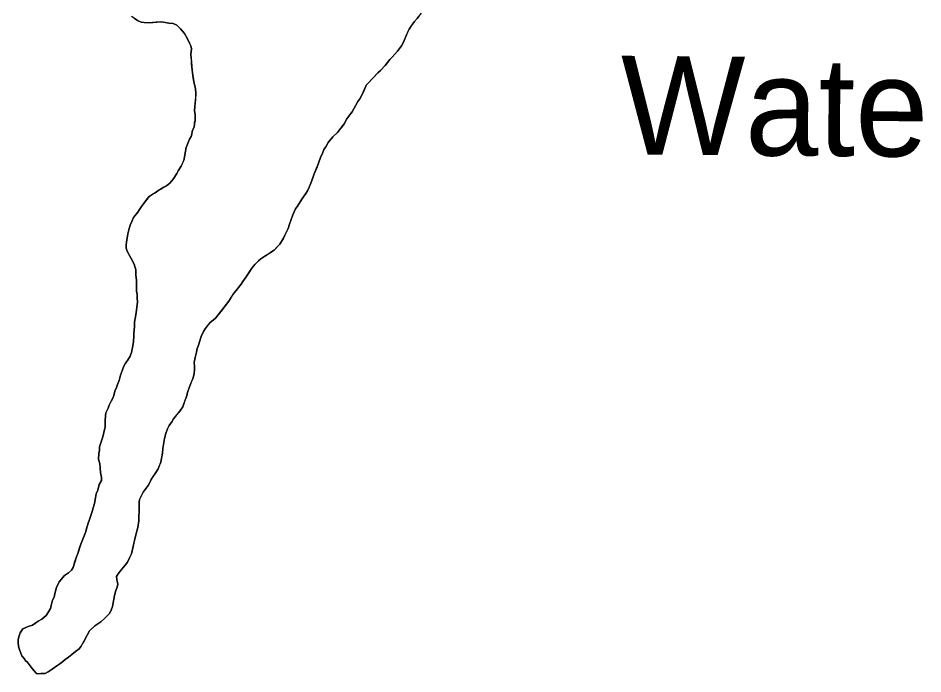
# Model space of a CAD drawing. Extents: x 3172297 to 3210190, y 958463 to 983887.
# Drawn here: x 3189904 to 3190821, y 968442 to 969107 of the extents above; entities that cross this region are included whole.
import ezdxf

# ---------------------------------------------------------------- set-up
doc = ezdxf.new("R2010")
doc.units = 0
for name, color, linetype in [('V-RIVR-IDEN', 7, 'Continuous'), ('V-SITE-VEGE', 7, 'Continuous'), ('V-TOPO-SHOR', 7, 'Continuous')]:
    doc.layers.add(name, color=color, linetype=linetype)

msp = doc.modelspace()

# ---------------------------------------------------------------- linework, layer by layer
at = {"layer": 'V-SITE-VEGE'}
for p, q in [((3190021.54, 969106.91), (3190025.11, 969104.47)), ((3190305.59, 969103.14), (3190308.63, 969106.41)), ((3190308.63, 969106.41), (3190312.89, 969111.76)), ((3190025.11, 969104.47), (3190028.69, 969102.63)), ((3190028.69, 969102.63), (3190031.69, 969102.29)), ((3190031.69, 969102.29), (3190036.8, 969102.24)), ((3190036.8, 969102.24), (3190048.52, 969103.01)), ((3190048.52, 969103.01), (3190051.52, 969102.67)), ((3190051.52, 969102.67), (3190056.62, 969101.72)), ((3190056.62, 969101.72), (3190061.11, 969101.37)), ((3190061.11, 969101.37), (3190065, 969099.82)), ((3190065, 969099.82), (3190068.56, 969096.18)), ((3190068.56, 969096.18), (3190072.71, 969091.33)), ((3190300.4, 969095.69), (3190305.59, 969103.14)), ((3190072.71, 969091.33), (3190075.66, 969085.89)), ((3190294.85, 969082.54), (3190297.02, 969088.22)), ((3190297.02, 969088.22), (3190300.4, 969095.69)), ((3190075.66, 969085.89), (3190077.71, 969081.36)), ((3190077.71, 969081.36), (3190079.18, 969078.64)), ((3190079.18, 969078.64), (3190079.75, 969075.63)), ((3190288.74, 969073.3), (3190292.71, 969078.96)), ((3190292.71, 969078.96), (3190294.85, 969082.54)), ((3190079.75, 969075.63), (3190079.08, 969069.93)), ((3190079.08, 969069.93), (3190080.41, 969054)), ((3190283.27, 969067.35), (3190288.74, 969073.3)), ((3190275.97, 969059.02), (3190280.84, 969064.97)), ((3190280.84, 969064.97), (3190283.27, 969067.35)), ((3190080.41, 969054), (3190080.95, 969049.19)), ((3190258.34, 969040.3), (3190268.67, 969051.3)), ((3190268.67, 969051.3), (3190271.41, 969053.97)), ((3190271.41, 969053.97), (3190275.97, 969059.02)), ((3190080.95, 969049.19), (3190082.36, 969041.06)), ((3190082.36, 969041.06), (3190083.8, 969035.34)), ((3190083.8, 969035.34), (3190084.05, 969030.84)), ((3190252.5, 969028.65), (3190256.51, 969037.92)), ((3190256.51, 969037.92), (3190256.82, 969038.82)), ((3190256.82, 969038.82), (3190258.34, 969040.3)), ((3190083.97, 969023.93), (3190083.3, 969017.33)), ((3190084.05, 969030.84), (3190083.97, 969023.93)), ((3190248.53, 969022.39), (3190250.36, 969025.07)), ((3190250.36, 969025.07), (3190252.5, 969028.65)), ((3190083.3, 969017.33), (3190082.95, 969012.83)), ((3190242.71, 969011.95), (3190244.55, 969015.53)), ((3190244.55, 969015.53), (3190246.38, 969018.51)), ((3190246.38, 969018.51), (3190248.53, 969022.39)), ((3190082.95, 969012.83), (3190083.51, 969009.22)), ((3190083.51, 969009.22), (3190083.43, 969002.31)), ((3190234.46, 968999.72), (3190237.22, 969004.8)), ((3190237.22, 969004.8), (3190242.71, 969011.95)), ((3190082.46, 968996.32), (3190080.93, 968993.33)), ((3190082.8, 968999.32), (3190082.46, 968996.32)), ((3190082.82, 969001.42), (3190082.8, 968999.32)), ((3190083.43, 969002.31), (3190082.82, 969001.42)), ((3190227.76, 968991.09), (3190234.46, 968999.72)), ((3190079.36, 968987.04), (3190077.83, 968984.36)), ((3190079.67, 968987.94), (3190079.36, 968987.04)), ((3190080.93, 968993.33), (3190079.67, 968987.94)), ((3190218.33, 968980.68), (3190222.9, 968986.64)), ((3190222.9, 968986.64), (3190227.76, 968991.09)), ((3190075.67, 968979.28), (3190074.42, 968975.69)), ((3190077.83, 968984.36), (3190075.67, 968979.28)), ((3190215.88, 968976.5), (3190218.33, 968980.68)), ((3190073.15, 968968.49), (3190072.49, 968963.99)), ((3190074.42, 968975.69), (3190073.15, 968968.49)), ((3190210.97, 968966.65), (3190212.5, 968969.64)), ((3190212.5, 968969.64), (3190214.05, 968973.82)), ((3190214.05, 968973.82), (3190215.88, 968976.5)), ((3190072.49, 968963.99), (3190069.41, 968956.82)), ((3190204.16, 968949.01), (3190208.18, 968958.88)), ((3190208.18, 968958.88), (3190210.97, 968966.65)), ((3190064.82, 968949.36), (3190061.15, 968943.7)), ((3190065.44, 968950.86), (3190064.82, 968949.36)), ((3190066.35, 968952.05), (3190065.44, 968950.86)), ((3190069.41, 968956.82), (3190066.35, 968952.05)), ((3190061.15, 968943.7), (3190057.81, 968939.53)), ((3190200.75, 968939.44), (3190204.16, 968949.01)), ((3190045.71, 968931.86), (3190042.98, 968929.79)), ((3190051.75, 968935.4), (3190045.71, 968931.86)), ((3190054.47, 968936.87), (3190051.75, 968935.4)), ((3190057.81, 968939.53), (3190054.47, 968936.87)), ((3190195.83, 968929.28), (3190197.37, 968931.97)), ((3190197.37, 968931.97), (3190199.21, 968935.55)), ((3190199.21, 968935.55), (3190200.75, 968939.44)), ((3190036.93, 968926.25), (3190031.15, 968918.81)), ((3190042.98, 968929.79), (3190036.93, 968926.25)), ((3190187.28, 968916.46), (3190191.56, 968923.32)), ((3190191.56, 968923.32), (3190195.83, 968929.28)), ((3190027.18, 968912.85), (3190025.34, 968910.16)), ((3190029.01, 968915.83), (3190027.18, 968912.85)), ((3190031.15, 968918.81), (3190029.01, 968915.83)), ((3190182.38, 968907.51), (3190185.15, 968913.48)), ((3190185.15, 968913.48), (3190187.28, 968916.46)), ((3190021.08, 968904.81), (3190019.23, 968900.92)), ((3190025.34, 968910.16), (3190021.08, 968904.81)), ((3190179.27, 968897.93), (3190182.38, 968907.51)), ((3190017.69, 968897.04), (3190016.13, 968892.25)), ((3190019.23, 968900.92), (3190017.69, 968897.04)), ((3190177.72, 968893.75), (3190179.27, 968897.93)), ((3190015.19, 968888.35), (3190013.89, 968879.96)), ((3190016.13, 968892.25), (3190015.19, 968888.35)), ((3190173.1, 968883.89), (3190177.72, 968893.75)), ((3190013.56, 968876.96), (3190013.52, 968873.66)), ((3190013.89, 968879.96), (3190013.56, 968876.96)), ((3190163.66, 968871.68), (3190169.43, 968877.92)), ((3190169.43, 968877.92), (3190173.1, 968883.89)), ((3190013.52, 968873.66), (3190014.69, 968870.64)), ((3190014.69, 968870.64), (3190017.04, 968866.41)), ((3190154.28, 968865.48), (3190163.66, 968871.68)), ((3190017.04, 968866.41), (3190018.51, 968863.09)), ((3190018.51, 968863.09), (3190021.75, 968857.35)), ((3190143.97, 968857.18), (3190147.62, 968860.75)), ((3190147.62, 968860.75), (3190150.04, 968862.82)), ((3190150.04, 968862.82), (3190154.28, 968865.48)), ((3190021.75, 968857.35), (3190023.19, 968851.63)), ((3190023.19, 968851.63), (3190023.44, 968846.82)), ((3190135.13, 968844.67), (3190140.93, 968853.32)), ((3190140.93, 968853.32), (3190143.97, 968857.18)), ((3190023.44, 968846.82), (3190023.97, 968841.11)), ((3190023.97, 968841.11), (3190023.88, 968833)), ((3190130.24, 968837.22), (3190131.77, 968839.9)), ((3190131.77, 968839.9), (3190135.13, 968844.67)), ((3190023.88, 968833), (3190024.15, 968829.99)), ((3190024.15, 968829.99), (3190024.71, 968826.98)), ((3190122.93, 968828.59), (3190125.06, 968830.97)), ((3190125.06, 968830.97), (3190130.24, 968837.22)), ((3190024.71, 968826.98), (3190024.67, 968823.38)), ((3190024.67, 968823.38), (3190024.92, 968818.88)), ((3190117.73, 968819.94), (3190122.93, 968828.59)), ((3190024.92, 968818.88), (3190023.93, 968810.78)), ((3190104.33, 968803.27), (3190117.73, 968819.94)), ((3190023.28, 968806.28), (3190022, 968798.79)), ((3190023.93, 968810.78), (3190023.28, 968806.28)), ((3190101.6, 968800.6), (3190104.33, 968803.27)), ((3190021.94, 968793.98), (3190021.27, 968787.68)), ((3190022, 968798.79), (3190021.94, 968793.98)), ((3190093.69, 968791.98), (3190098.57, 968798.23)), ((3190098.57, 968798.23), (3190101.6, 968800.6)), ((3190021.23, 968784.38), (3190020.87, 968778.98)), ((3190021.27, 968787.68), (3190021.23, 968784.38)), ((3190086.9, 968775.54), (3190089.4, 968784.22)), ((3190089.4, 968784.22), (3190091.86, 968789.29)), ((3190091.86, 968789.29), (3190093.69, 968791.98)), ((3190020.87, 968778.98), (3190020.23, 968774.78)), ((3190085.36, 968771.95), (3190086.9, 968775.54)), ((3190018.95, 968767.89), (3190017.71, 968764.3)), ((3190020.23, 968774.78), (3190018.95, 968767.89)), ((3190083.46, 968762.96), (3190084.72, 968768.35)), ((3190084.72, 968768.35), (3190085.36, 968771.95)), ((3190012.82, 968757.15), (3190010.98, 968753.56)), ((3190014.95, 968759.82), (3190012.82, 968757.15)), ((3190017.71, 968764.3), (3190014.95, 968759.82)), ((3190082.5, 968757.87), (3190083.46, 968762.96)), ((3190082.76, 968753.66), (3190082.5, 968757.87)), ((3190009.74, 968750.57), (3190007.88, 968744.89)), ((3190010.98, 968753.56), (3190009.74, 968750.57)), ((3190082.38, 968746.76), (3190082.72, 968750.66)), ((3190082.72, 968750.66), (3190082.76, 968753.66)), ((3190006.32, 968739.5), (3190004.77, 968735.61)), ((3190007.88, 968744.89), (3190006.32, 968739.5)), ((3190078.34, 968734.79), (3190081.43, 968742.26)), ((3190081.43, 968742.26), (3190082.38, 968746.76)), ((3190003.84, 968732.62), (3190002, 968728.73)), ((3190004.77, 968735.61), (3190003.84, 968732.62)), ((3190075.55, 968727.31), (3190078.34, 968734.79)), ((3190000.11, 968721.55), (3189998.27, 968718.57)), ((3190001.04, 968724.54), (3190000.11, 968721.55)), ((3190002, 968728.73), (3190001.04, 968724.54)), ((3190071.82, 968715.94), (3190074.6, 968723.12)), ((3190074.6, 968723.12), (3190075.55, 968727.31)), ((3189995.19, 968711.39), (3189993.04, 968706.91)), ((3189996.43, 968714.68), (3189995.19, 968711.39)), ((3189998.27, 968718.57), (3189996.43, 968714.68)), ((3190068.75, 968709.67), (3190070.89, 968712.95)), ((3190070.89, 968712.95), (3190071.82, 968715.94)), ((3189992.7, 968703.61), (3189992.35, 968699.11)), ((3189993.04, 968706.91), (3189992.41, 968703.92)), ((3189992.41, 968703.92), (3189992.7, 968703.61)), ((3190061.44, 968700.74), (3190066.92, 968707.29)), ((3190066.92, 968707.29), (3190068.75, 968709.67)), ((3189992.28, 968692.51), (3189990.71, 968686.82)), ((3189992.35, 968699.11), (3189992.28, 968692.51)), ((3190055.32, 968690.6), (3190057.16, 968693.88)), ((3190057.16, 968693.88), (3190059.91, 968697.76)), ((3190059.91, 968697.76), (3190061.44, 968700.74)), ((3189990.71, 968686.82), (3189989.76, 968682.62)), ((3190052.51, 968680.72), (3190053.77, 968685.81)), ((3190053.77, 968685.81), (3190055.32, 968690.6)), ((3189988.21, 968677.54), (3189986.35, 968672.45)), ((3189989.76, 968682.62), (3189988.21, 968677.54)), ((3190050.59, 968670.53), (3190052.51, 968680.72)), ((3189985.97, 968665.55), (3189985.6, 968659.85)), ((3189986.31, 968669.15), (3189985.97, 968665.55)), ((3189986.35, 968672.45), (3189986.31, 968669.15)), ((3190048.64, 968656.74), (3190050.24, 968666.03)), ((3190050.24, 968666.03), (3190050.59, 968670.53)), ((3189985.6, 968659.85), (3189986.75, 968655.03)), ((3190045.86, 968650.16), (3190048.64, 968656.74)), ((3189986.75, 968655.03), (3189987.01, 968651.12)), ((3189987.01, 968651.12), (3189987.56, 968646.31)), ((3190043.71, 968646.28), (3190045.86, 968650.16)), ((3189988.36, 968638.19), (3189986.22, 968634.31)), ((3189987.56, 968646.31), (3189988.4, 968641.2)), ((3189988.4, 968641.2), (3189988.36, 968638.19)), ((3190037.6, 968636.14), (3190038.83, 968639.13)), ((3190038.83, 968639.13), (3190043.71, 968646.28)), ((3189984.65, 968628.32), (3189983.11, 968624.74)), ((3189986.22, 968634.31), (3189984.65, 968628.32)), ((3190030.88, 968626.31), (3190033.63, 968630.48)), ((3190033.63, 968630.48), (3190035.76, 968633.16)), ((3190035.76, 968633.16), (3190037.6, 968636.14)), ((3189983.11, 968624.74), (3189981.5, 968614.85)), ((3190026.89, 968618.84), (3190030.88, 968626.31)), ((3189979.95, 968610.66), (3189979.01, 968606.76)), ((3189981.5, 968614.85), (3189979.95, 968610.66)), ((3190026.56, 968615.84), (3190026.89, 968618.84)), ((3190026.82, 968612.24), (3190026.56, 968615.84)), ((3190026.76, 968607.13), (3190026.82, 968612.24)), ((3189979.01, 968606.76), (3189976.82, 968599.58)), ((3190026.35, 968597.23), (3190026.4, 968601.43)), ((3190026.4, 968601.43), (3190026.76, 968607.13)), ((3189974.66, 968593.9), (3189972.16, 968585.52)), ((3189976.82, 968599.58), (3189974.66, 968593.9)), ((3190025.38, 968590.63), (3190026.35, 968597.23)), ((3189972.16, 968585.52), (3189969.68, 968578.64)), ((3190022.56, 968580.45), (3190025.38, 968590.63)), ((3189967.52, 968573.56), (3189964.42, 968564.28)), ((3189969.68, 968578.64), (3189967.52, 968573.56)), ((3190019.7, 968566.97), (3190022.56, 968580.45)), ((3189964.42, 968564.28), (3189963.18, 968560.99)), ((3190016.92, 968559.79), (3190018.77, 968563.98)), ((3190018.77, 968563.98), (3190019.7, 968566.97)), ((3189963.18, 968560.99), (3189959.75, 968550.22)), ((3190012.63, 968552.33), (3190014.77, 968555.61)), ((3190014.77, 968555.61), (3190016.92, 968559.79)), ((3189957.92, 968547.24), (3189954.89, 968544.57)), ((3189959.75, 968550.22), (3189957.92, 968547.24)), ((3190005.33, 968543.7), (3190007.46, 968546.38)), ((3190007.46, 968546.38), (3190012.63, 968552.33)), ((3189950.95, 968541.91), (3189945.48, 968535.66)), ((3189954.89, 968544.57), (3189950.95, 968541.91)), ((3190003.8, 968541.02), (3190005.33, 968543.7)), ((3190004.06, 968538.01), (3190003.8, 968541.02)), ((3190004.91, 968533.2), (3190004.06, 968538.01)), ((3189943.01, 968529.69), (3189941.46, 968525.2)), ((3189945.48, 968535.66), (3189943.01, 968529.69)), ((3190003.04, 968526.91), (3190004.28, 968530.2)), ((3190004.28, 968530.2), (3190004.91, 968533.2)), ((3189940.5, 968520.1), (3189938.96, 968516.82)), ((3189941.46, 968525.2), (3189940.5, 968520.1)), ((3190000.5, 968514.33), (3190001.78, 968521.82)), ((3190001.78, 968521.82), (3190003.04, 968526.91)), ((3189937.4, 968511.43), (3189936.76, 968508.43)), ((3189938.96, 968516.82), (3189937.4, 968511.43)), ((3189998.31, 968506.84), (3189999.55, 968510.44)), ((3189999.55, 968510.44), (3190000.5, 968514.33)), ((3189932.48, 968501.57), (3189927.94, 968497.72)), ((3189934.93, 968505.15), (3189932.48, 968501.57)), ((3189936.76, 968508.43), (3189934.93, 968505.15)), ((3189991.61, 968498.21), (3189996.47, 968503.56)), ((3189996.47, 968503.56), (3189998.31, 968506.84)), ((3189918.55, 968491.52), (3189914.04, 968490.37)), ((3189924.31, 968495.66), (3189918.55, 968491.52)), ((3189927.94, 968497.72), (3189924.31, 968495.66)), ((3189976.45, 968485.77), (3189981.91, 968490.81)), ((3189981.91, 968490.81), (3189984.94, 968492.88)), ((3189984.94, 968492.88), (3189987.67, 968494.95)), ((3189987.67, 968494.95), (3189991.61, 968498.21)), ((3189906.16, 968483.85), (3189904.61, 968479.66)), ((3189908.91, 968488.02), (3189906.16, 968483.85)), ((3189914.04, 968490.37), (3189908.91, 968488.02)), ((3189970.93, 968475.62), (3189974, 968481.59)), ((3189974, 968481.59), (3189976.45, 968485.77)), ((3189903.97, 968476.67), (3189903.94, 968473.67)), ((3189903.94, 968473.67), (3189904.21, 968470.66)), ((3189904.61, 968479.66), (3189903.97, 968476.67)), ((3189967.87, 968470.25), (3189970.93, 968475.62)), ((3189904.21, 968470.66), (3189905.08, 968467.65)), ((3189905.08, 968467.65), (3189907.7, 968460.41)), ((3189955.13, 968459.28), (3189962.1, 968464.91)), ((3189962.1, 968464.91), (3189965.74, 968467.57)), ((3189965.74, 968467.57), (3189967.87, 968470.25)), ((3189907.7, 968460.41), (3189910.07, 968457.68)), ((3189910.07, 968457.68), (3189911.84, 968455.26)), ((3189911.84, 968455.26), (3189912.74, 968454.65)), ((3189912.74, 968454.65), (3189914.22, 968453.13)), ((3189946.35, 968452.47), (3189949.07, 968454.54)), ((3189949.07, 968454.54), (3189951.81, 968456.91)), ((3189951.81, 968456.91), (3189955.13, 968459.28)), ((3189914.22, 968453.13), (3189917.18, 968449.19)), ((3189917.18, 968449.19), (3189918.66, 968447.37)), ((3189918.66, 968447.37), (3189919.84, 968445.56)), ((3189919.84, 968445.56), (3189922.22, 968442.83)), ((3189934.54, 968444.19), (3189938.48, 968446.85)), ((3189938.48, 968446.85), (3189943.32, 968450.4)), ((3189943.32, 968450.4), (3189946.35, 968452.47)), ((3189922.22, 968442.83), (3189923.41, 968442.21)), ((3189923.41, 968442.21), (3189931.52, 968442.72)), ((3189931.52, 968442.72), (3189934.54, 968444.19))]:
    msp.add_line(p, q, dxfattribs=at)
at = {"layer": 'V-TOPO-SHOR'}
for points in [[(3190031.7, 969102.29), (3190028.69, 969102.63), (3190025.11, 969104.47), (3190021.54, 969106.91), (3190018.85, 969108.45)], [(3190310.76, 969109.09), (3190308.63, 969106.41), (3190305.59, 969103.14), (3190302.84, 969099.26), (3190300.4, 969095.69), (3190298.86, 969092.4), (3190297.02, 969088.22), (3190294.85, 969082.54), (3190292.71, 969078.96), (3190288.74, 969073.3), (3190283.27, 969067.35), (3190280.84, 969064.97), (3190275.97, 969059.02), (3190271.41, 969053.97), (3190268.67, 969051.3), (3190265.02, 969047.43), (3190258.34, 969040.3), (3190256.82, 969038.82), (3190256.51, 969037.92), (3190253.74, 969031.64), (3190252.5, 969028.65), (3190250.36, 969025.07), (3190248.53, 969022.39), (3190246.38, 969018.51), (3190244.55, 969015.53), (3190242.71, 969011.95), (3190239.96, 969008.37), (3190237.22, 969004.8), (3190234.46, 968999.72), (3190231.72, 968996.15), (3190229.59, 968993.47), (3190227.76, 968991.09), (3190222.9, 968986.64), (3190218.33, 968980.68), (3190215.88, 968976.51), (3190214.05, 968973.82), (3190212.5, 968969.64), (3190210.97, 968966.65), (3190208.18, 968958.88), (3190206.33, 968954.39), (3190204.16, 968949.01), (3190202.3, 968943.93), (3190200.75, 968939.44), (3190199.21, 968935.55), (3190197.37, 968931.97), (3190195.83, 968929.28), (3190191.56, 968923.32), (3190187.28, 968916.46), (3190185.15, 968913.48), (3190182.38, 968907.51), (3190179.27, 968897.93), (3190177.72, 968893.75), (3190176.18, 968890.46), (3190173.1, 968883.89), (3190169.43, 968877.92), (3190166.39, 968874.65), (3190163.66, 968871.68), (3190160.93, 968869.91), (3190158.21, 968868.14), (3190154.28, 968865.48), (3190150.04, 968862.82)], [(3190009.74, 968750.57), (3190010.98, 968753.56), (3190012.82, 968757.15), (3190014.95, 968759.82), (3190017.71, 968764.3), (3190018.95, 968767.89), (3190020.23, 968774.78), (3190020.87, 968778.98), (3190021.23, 968784.38), (3190021.27, 968787.68), (3190021.94, 968793.98), (3190022, 968798.79), (3190023.28, 968806.28), (3190023.93, 968810.78), (3190024.27, 968813.78), (3190024.92, 968818.87), (3190024.67, 968823.38), (3190024.71, 968826.99), (3190024.15, 968829.99), (3190023.88, 968833), (3190023.93, 968837.2), (3190023.97, 968841.11), (3190023.43, 968846.82), (3190023.19, 968851.63), (3190021.75, 968857.35), (3190018.51, 968863.09), (3190017.04, 968866.41), (3190014.69, 968870.64), (3190013.52, 968873.66), (3190013.56, 968876.66), (3190013.56, 968876.96), (3190013.89, 968879.96), (3190015.19, 968888.35), (3190016.13, 968892.25), (3190017.69, 968897.04), (3190019.23, 968900.92), (3190021.08, 968904.81), (3190022.91, 968907.19), (3190025.34, 968910.16), (3190027.18, 968912.85), (3190029.01, 968915.83), (3190031.15, 968918.81), (3190034.8, 968923.57), (3190036.93, 968926.25), (3190039.96, 968928.02), (3190042.98, 968929.79), (3190045.71, 968931.86), (3190048.73, 968933.63), (3190051.75, 968935.4), (3190054.47, 968936.87), (3190057.81, 968939.53), (3190061.15, 968943.7), (3190064.82, 968949.36), (3190065.44, 968950.86), (3190066.35, 968952.05), (3190069.41, 968956.82), (3190071.26, 968961.01), (3190072.49, 968963.99), (3190073.14, 968968.49), (3190073.78, 968972.09), (3190074.42, 968975.69), (3190075.67, 968979.28), (3190077.83, 968984.36), (3190079.36, 968987.04), (3190079.67, 968987.94), (3190080.93, 968993.33), (3190082.46, 968996.32), (3190082.8, 968999.32), (3190082.82, 969001.42), (3190083.43, 969002.31), (3190083.48, 969006.22), (3190083.51, 969009.22), (3190082.95, 969012.83), (3190083.3, 969017.33), (3190083.97, 969023.93), (3190084.01, 969026.93), (3190084.05, 969030.84), (3190083.8, 969035.34), (3190082.36, 969041.06), (3190081.52, 969046.18), (3190080.95, 969049.19), (3190080.41, 969054), (3190080.15, 969057.61), (3190079.88, 969060.61), (3190079.62, 969064.22), (3190079.08, 969069.93), (3190079.75, 969075.63), (3190079.18, 969078.64), (3190077.71, 969081.36), (3190075.66, 969085.89), (3190072.71, 969091.33), (3190068.56, 969096.18), (3190065, 969099.82), (3190061.11, 969101.36), (3190056.62, 969101.72), (3190051.52, 969102.67), (3190048.52, 969103.01), (3190044.01, 969102.76), (3190040.11, 969102.5), (3190036.8, 969102.24), (3190031.7, 969102.29)], [(3190150.04, 968862.82), (3190147.62, 968860.75), (3190143.97, 968857.18), (3190140.93, 968853.32), (3190137.88, 968848.84), (3190135.13, 968844.67), (3190131.77, 968839.9), (3190130.24, 968837.22), (3190127.5, 968833.95), (3190125.06, 968830.97), (3190122.93, 968828.59), (3190121.1, 968825.61), (3190117.73, 968819.94), (3190114.38, 968815.77), (3190111.03, 968811.6), (3190107.98, 968807.73), (3190104.33, 968803.27), (3190101.6, 968800.6), (3190098.57, 968798.23), (3190096.44, 968795.55), (3190093.69, 968791.98), (3190091.86, 968789.29), (3190089.4, 968784.22), (3190086.9, 968775.54), (3190085.36, 968771.95), (3190084.72, 968768.35), (3190083.46, 968762.96), (3190082.5, 968757.87), (3190082.76, 968753.66), (3190082.72, 968750.66), (3190082.38, 968746.76), (3190081.43, 968742.26), (3190079.88, 968738.68), (3190078.34, 968734.79), (3190076.79, 968730.6), (3190075.55, 968727.31), (3190074.6, 968723.12), (3190073.06, 968719.23), (3190071.82, 968715.94), (3190070.89, 968712.95), (3190068.75, 968709.67), (3190066.92, 968707.29), (3190064.18, 968704.02), (3190061.44, 968700.74), (3190059.91, 968697.76), (3190057.16, 968693.88), (3190055.32, 968690.6), (3190053.77, 968685.81), (3190052.51, 968680.72), (3190050.59, 968670.53), (3190050.24, 968666.03), (3190049.6, 968662.44), (3190048.64, 968656.74), (3190047.4, 968653.75), (3190045.86, 968650.16), (3190043.71, 968646.28), (3190040.66, 968641.81), (3190038.83, 968639.13), (3190037.6, 968636.14), (3190035.76, 968633.16), (3190033.63, 968630.48), (3190030.88, 968626.31), (3190028.43, 968621.83), (3190026.89, 968618.84), (3190026.56, 968615.84), (3190026.82, 968612.24), (3190026.76, 968607.13), (3190026.4, 968601.43), (3190026.35, 968597.23), (3190025.38, 968590.63), (3190024.43, 968587.04), (3190022.56, 968580.45), (3190021.29, 968574.76), (3190020.65, 968571.46), (3190019.7, 968566.97), (3190018.77, 968563.98), (3190016.92, 968559.79), (3190014.77, 968555.61), (3190012.63, 968552.33), (3190007.46, 968546.38), (3190005.33, 968543.7), (3190003.8, 968541.02), (3190004.06, 968538.01), (3190004.91, 968533.2), (3190004.28, 968530.2), (3190003.04, 968526.91), (3190001.78, 968521.82), (3190000.5, 968514.33), (3189999.55, 968510.44), (3189998.31, 968506.84), (3189996.78, 968504.16), (3189996.47, 968503.56), (3189991.61, 968498.21), (3189987.67, 968494.95), (3189984.94, 968492.88), (3189981.91, 968490.81), (3189976.45, 968485.77), (3189974, 968481.59), (3189972.47, 968478.6), (3189970.93, 968475.62), (3189969.4, 968472.93)], [(3189969.4, 968472.93), (3189967.87, 968470.25), (3189965.74, 968467.57), (3189962.1, 968464.91), (3189958.47, 968461.94), (3189955.13, 968459.28), (3189951.8, 968456.91), (3189949.07, 968454.54), (3189946.35, 968452.47), (3189943.32, 968450.4), (3189940.9, 968448.62), (3189938.48, 968446.85), (3189934.54, 968444.19), (3189931.52, 968442.72), (3189927.02, 968442.47), (3189923.41, 968442.21), (3189922.22, 968442.83), (3189919.84, 968445.56), (3189918.66, 968447.37), (3189917.18, 968449.19), (3189914.22, 968453.13), (3189912.74, 968454.65), (3189911.84, 968455.26), (3189910.07, 968457.68), (3189907.7, 968460.41), (3189906.24, 968464.33), (3189905.08, 968467.65), (3189904.21, 968470.66), (3189903.94, 968473.67), (3189903.97, 968476.67), (3189904.61, 968479.66), (3189906.16, 968483.85), (3189908.91, 968488.02), (3189914.04, 968490.37), (3189918.56, 968491.52), (3189921.89, 968493.89), (3189924.31, 968495.66), (3189927.94, 968497.72), (3189932.48, 968501.57), (3189934.93, 968505.15), (3189936.76, 968508.43), (3189937.4, 968511.43), (3189938.96, 968516.82), (3189940.5, 968520.1), (3189941.46, 968525.2), (3189943.01, 968529.69), (3189944.24, 968532.68), (3189945.48, 968535.66), (3189948.82, 968539.53), (3189950.95, 968541.91), (3189954.89, 968544.57), (3189957.92, 968547.24), (3189959.75, 968550.22), (3189961.62, 968556.21), (3189963.18, 968560.99), (3189964.42, 968564.28), (3189966.28, 968569.97), (3189967.52, 968573.56), (3189969.68, 968578.64), (3189970.92, 968582.23), (3189972.16, 968585.52), (3189973.72, 968590.61), (3189974.66, 968593.9), (3189976.82, 968599.58), (3189978.07, 968603.77), (3189979.01, 968606.76), (3189979.95, 968610.66), (3189981.5, 968614.85), (3189982.46, 968620.54), (3189983.11, 968624.74), (3189984.65, 968628.32), (3189986.22, 968634.31), (3189988.37, 968638.19), (3189988.4, 968641.2), (3189987.56, 968646.31), (3189987.01, 968651.12), (3189986.75, 968655.03), (3189985.6, 968659.85), (3189985.97, 968665.55), (3189986.31, 968669.15), (3189986.35, 968672.45), (3189988.21, 968677.54), (3189989.76, 968682.62), (3189990.71, 968686.82), (3189992.28, 968692.51), (3189992.35, 968699.11), (3189992.7, 968703.61), (3189992.41, 968703.92), (3189993.04, 968706.91), (3189993.35, 968707.51), (3189995.19, 968711.39), (3189996.43, 968714.68), (3189998.27, 968718.57), (3190000.11, 968721.55), (3190001.04, 968724.54), (3190001.99, 968728.73), (3190003.84, 968732.62), (3190004.77, 968735.61), (3190006.32, 968739.5), (3190007.88, 968744.89), (3190009.74, 968750.57)]]:
    msp.add_lwpolyline(points, dxfattribs=at)

# ---------------------------------------------------------------- texts
at = {"layer": 'V-RIVR-IDEN'}
msp.add_text('Water', height=100, rotation=359.59375, dxfattribs=at).set_placement((3190514.56, 968968.75))

doc.saveas('drawing.dxf')
